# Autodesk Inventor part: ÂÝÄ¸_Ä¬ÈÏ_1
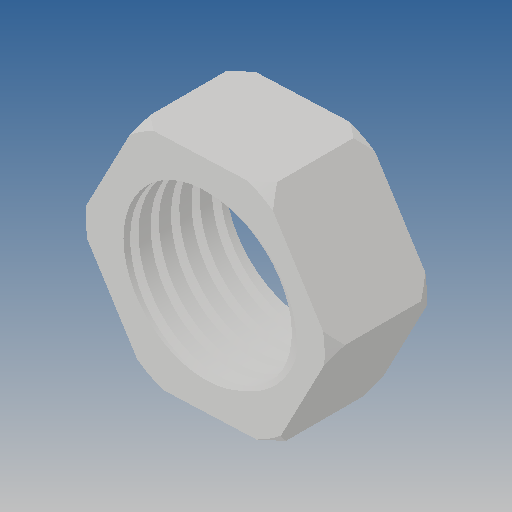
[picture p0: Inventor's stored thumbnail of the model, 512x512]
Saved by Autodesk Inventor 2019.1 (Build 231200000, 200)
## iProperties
Created: 2012-10
Part Number: ÂÝÄ¸_Ä¬ÈÏ_1
Material: Ogólny
Document SubType Name: Modeling
Designer: CADENGINEERING4
Density: 1 g/cm^3
Appearance: Domyślna
Author: CADENGINEERING4
Revision Number: ÈÎºÎ
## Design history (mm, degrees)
feature "NONE"
node "Bryła1"
